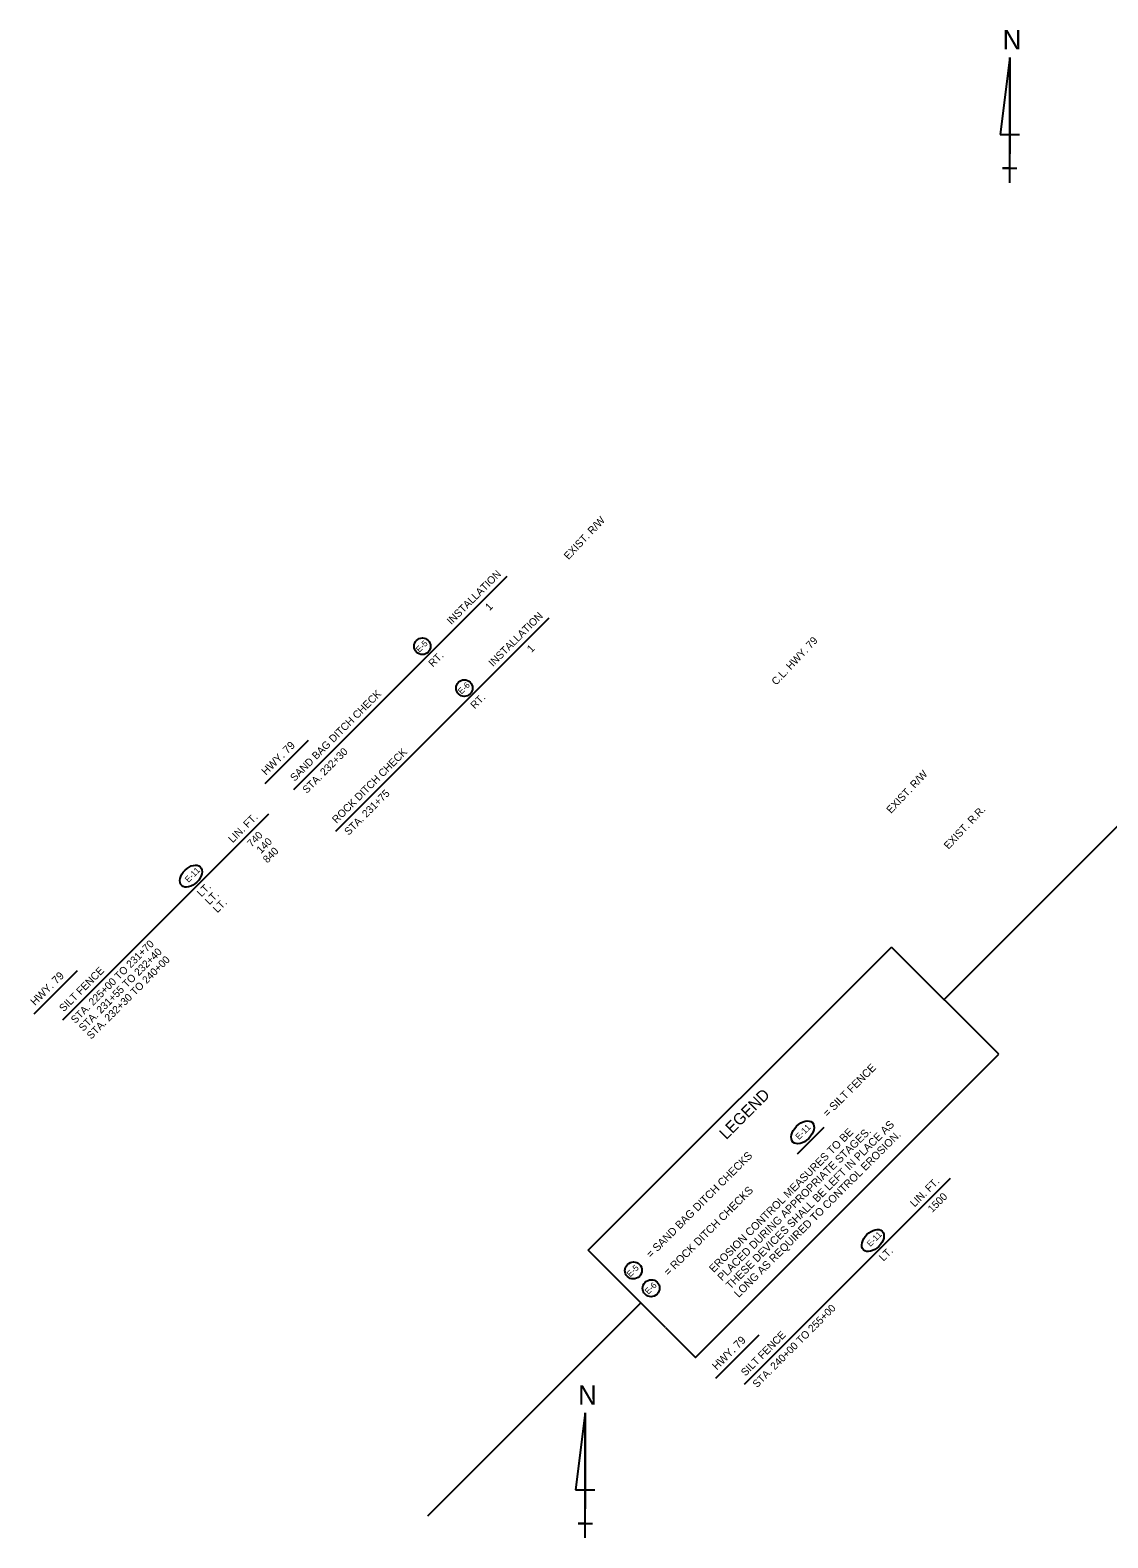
# Model space of a CAD drawing. Extents: x 1388120 to 1389841, y 1944307 to 1945760.
# Drawn here: x 1388120 to 1388980, y 1944307 to 1945511 of the extents above; entities that cross this region are included whole.
import ezdxf

# ---------------------------------------------------------------- set-up
doc = ezdxf.new("R2010")
doc.units = 0
for name, color, linetype in [('1', 7, 'Continuous'), ('44', 7, 'Continuous'), ('63', 7, 'Continuous'), ('Level 1', 7, 'Continuous'), ('Level 44', 7, 'Continuous'), ('R_Draft', 7, 'Continuous')]:
    doc.layers.add(name, color=color, linetype=linetype)

msp = doc.modelspace()

# ---------------------------------------------------------------- linework, layer by layer
at = {"layer": '1'}
for p, q in [((1388849.6, 1944736.7), (1389051.9, 1944939.1)), ((1388565.3, 1944536.4), (1388807.6, 1944778.6)), ((1388893.2, 1944693.1), (1388807.6, 1944778.6)), ((1388627, 1944474.7), (1388565.3, 1944536.4)), ((1388437.2, 1944324.3), (1388607.3, 1944494.4))]:
    msp.add_line(p, q, dxfattribs=at)
msp.add_lwpolyline([(1388627, 1944474.7), (1388650.9, 1944450.8), (1388893.2, 1944693.1)], dxfattribs=at)
for centre in [(1388432.8, 1945018.8), (1388466.3, 1944985.4)]:
    msp.add_circle(centre, 6.61, dxfattribs=at)
for centre in [(1388248, 1944835.2), (1388792.6, 1944544.2)]:
    msp.add_ellipse(centre, major_axis=(7.44, 7.44), ratio=0.638788, dxfattribs=at)
at = {"layer": '44'}
for p, q in [((1388330.1, 1944904.5), (1388500.5, 1945074.9)), ((1388363.6, 1944871), (1388534, 1945041.4)), ((1388307.3, 1944909.3), (1388341.8, 1944943.9)), ((1388145.6, 1944720.4), (1388310.2, 1944885)), ((1388122.7, 1944725.3), (1388157.3, 1944759.8)), ((1388690.1, 1944429.5), (1388854.7, 1944594.1)), ((1388667.3, 1944434.3), (1388701.8, 1944468.9))]:
    msp.add_line(p, q, dxfattribs=at)
at = {"layer": '63'}
for p, q in [((1388902, 1945489), (1388894.3, 1945427.5)), ((1388902, 1945389), (1388902, 1945489)), ((1388902, 1945489), (1388902, 1945412.1)), ((1388894.3, 1945427.5), (1388909.7, 1945427.5)), ((1388902, 1945389), (1388902, 1945412.1)), ((1388902, 1945400.6), (1388896.2, 1945400.6)), ((1388896.2, 1945400.6), (1388907.7, 1945400.6)), ((1388902, 1945389), (1388902, 1945400.6)), ((1388562.8, 1944406.7), (1388555.2, 1944345.2)), ((1388562.8, 1944306.7), (1388562.8, 1944406.7)), ((1388562.8, 1944406.7), (1388562.8, 1944329.8)), ((1388555.2, 1944345.2), (1388570.5, 1944345.2)), ((1388562.8, 1944306.7), (1388562.8, 1944329.8)), ((1388562.8, 1944318.3), (1388557.1, 1944318.3)), ((1388557.1, 1944318.3), (1388568.6, 1944318.3)), ((1388562.8, 1944306.7), (1388562.8, 1944318.3))]:
    msp.add_line(p, q, dxfattribs=at)
at = {"layer": 'Level 1'}
for centre, major_axis, ratio in [((1388736.5, 1944630.6), (7.75, 7.75), 0.622952), ((1388601.4, 1944520.3), (-4.87, -4.86), 0.97521), ((1388615.5, 1944506.1), (-4.87, -4.86), 0.97521)]:
    msp.add_ellipse(centre, major_axis=major_axis, ratio=ratio, dxfattribs=at)
at = {"layer": 'Level 44'}
msp.add_lwpolyline([(1388732.4, 1944613.3), (1388753.7, 1944634.6)], dxfattribs=at)

# ---------------------------------------------------------------- texts
at = {"layer": '1'}
for s, p in [('E-5 ', (1388430.4, 1945013.5)), ('E-6 ', (1388464.1, 1944980.2)), ('E-11', (1388246, 1944829.8)), ('E-11', (1388790.6, 1944538.9))]:
    msp.add_text(s, height=4.8, rotation=45, dxfattribs=at).set_placement(p)
at = {"layer": '44'}
for s, height, p in [('INSTALLATION', 6, (1388455.9, 1945035.6)), ('1', 6, (1388486.5, 1945046.8)), ('INSTALLATION', 6, (1388489.3, 1945002.1)), ('1', 6, (1388519.9, 1945013.3)), ('RT.', 6, (1388441.2, 1945001.8)), ('SAND BAG DITCH CHECK', 6, (1388330.8, 1944910.5)), ('RT.', 6, (1388474.7, 1944968.3)), ('HWY. 79', 6.25, (1388308, 1944915.4)), ('STA. 232+30', 6, (1388340.5, 1944900.8)), ('ROCK DITCH CHECK', 6, (1388364.3, 1944877)), ('STA. 231+75', 6, (1388374, 1944867.4)), ('LIN. FT.', 6, (1388281.3, 1944861.4)), ('740', 6, (1388296.4, 1944857.9)), ('140', 6, (1388303.9, 1944852.8)), ('840', 6, (1388309, 1944845.2)), ('LT.', 6, (1388256.4, 1944818.2)), ('LT.', 6, (1388262.7, 1944811.8)), ('LT.', 6, (1388269.1, 1944805.5)), ('STA. 225+00 TO 231+70', 6, (1388155.6, 1944717.1)), ('STA. 231+55 TO 232+40', 6, (1388161.9, 1944710.8)), ('SILT FENCE      ', 6, (1388146.3, 1944726.4)), ('STA. 232+30 TO 240+00', 6, (1388168.3, 1944704.5)), ('HWY. 79', 6.25, (1388123.5, 1944731.4)), ('LIN. FT.', 6, (1388825.8, 1944570.5)), ('1500', 6, (1388840, 1944566.1)), ('LT.', 6, (1388801, 1944527.2)), ('STA. 240+00 TO 255+00', 6, (1388700.1, 1944426.2)), ('HWY. 79', 6.25, (1388668, 1944440.4)), ('SILT FENCE      ', 6, (1388690.8, 1944435.5))]:
    msp.add_text(s, height=height, rotation=45, dxfattribs=at).set_placement(p)
at = {"layer": '63'}
for p in [(1388896.3, 1945495.5), (1388557.2, 1944413.1)]:
    msp.add_text('N', height=15.4, rotation=360, dxfattribs=at).set_placement(p)
at = {"layer": 'Level 1'}
for s, height, p in [('= SILT FENCE', 6.25, (1388756.4, 1944642.4)), ('EROSION CONTROL MEASURES TO BE', 6.25, (1388665.5, 1944518.2)), ('PLACED DURING APPROPRIATE STAGES. ', 6.25, (1388672.2, 1944511.5)), ('THESE DEVICES SHALL BE LEFT IN PLACE AS ', 6.25, (1388678.8, 1944504.9)), ('LONG AS REQUIRED TO CONTROL EROSION.', 6.25, (1388685.5, 1944498.2)), ('E-11 ', 4.88, (1388733.6, 1944624.4)), ('= SAND BAG DITCH CHECKS', 6.25, (1388615.3, 1944529.8)), ('= ROCK DITCH CHECKS', 6.25, (1388629.4, 1944515.6)), ('E-5 ', 4.88, (1388598.9, 1944514.7)), ('E-6 ', 4.88, (1388613.2, 1944500.8))]:
    msp.add_text(s, height=height, rotation=45, dxfattribs=at).set_placement(p)
at = {"layer": 'Level 44'}
msp.add_text('LEGEND', height=9.14, rotation=45, dxfattribs=at).set_placement((1388675.5, 1944624.3))
at = {"layer": 'R_Draft'}
for s, rotation, p in [('EXIST. R/W', 46.6607, (1388549.5, 1945087.5)), ('C.L. HWY. 79', 46.736, (1388715.4, 1944987.2)), ('EXIST. R/W', 46.6607, (1388807.1, 1944884.8)), ('EXIST. R.R.', 46.6607, (1388853, 1944856.2))]:
    msp.add_text(s, height=6, rotation=rotation, dxfattribs=at).set_placement(p)

doc.saveas('drawing.dxf')
